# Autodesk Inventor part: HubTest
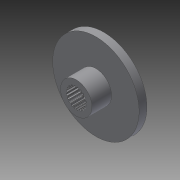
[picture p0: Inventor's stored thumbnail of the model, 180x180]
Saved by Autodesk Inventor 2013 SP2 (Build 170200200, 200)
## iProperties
Created: 2020-02
Part Number: HubTest
Material: Generic
Document SubType Name: Modeling
Designer: DELL
Density: 1 g/cm^3
Author: DELL
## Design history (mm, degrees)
sketch "Sketch1" dims "d2" = 4.61623
  geometry: C1 r 4 at (0, 0); C2 r 2.6 at (0, 0); A1 r 2.308 centre (0, 0) between (0.414, 2.271) and (0.308, 2.287); A2 r 1.037 centre (-0.708, 1.95) between (0.259, 2.327) and (0.255, 2.336); A3 r 0.063 centre (0.317, 2.349) between (0.259, 2.327) and (0.308, 2.287); A4 r 0.062 centre (0.425, 2.332) between (0.414, 2.271) and (0.473, 2.293); A5 r 1.037 centre (1.276, 1.636) between (0.48, 2.301) and (0.473, 2.293); A6 r 1.037 centre (1.276, 1.636) between (0.706, 2.502) and (0.473, 2.293); A7 r 2.6 centre (0, 0) between (0.706, 2.502) and (0.102, 2.598); 2 further points
  constraints: 14 point on circle, 9 centre point, 5 coincident, 6 other
  dimensions: "d3" = 8 diameter of C1; "d8" = 5.2 diameter of C2
extrude "Extrusion1" new body sketch "Sketch1" distance "d4" = 5; taper "d5" = 0 deg
sketch "Sketch5"
  geometry: C1 r 2.6 at (0, 0) reference; 1 further point
extrude "Extrusion4" join sketch "Sketch5" distance "d32" = 1.5; taper "d33" = 0 deg
sketch "Sketch2"
  geometry: L1 (0, -5.6)-(0, 5.6) reference; A1 r 2.6 centre (0, 0) between (0.306, 2.582) and (-0.306, 2.582); A2 r 0.063 centre (-0.055, 2.37) between (-0.108, 2.338) and (-0.053, 2.308); A3 r 0.062 centre (0.055, 2.37) between (0.053, 2.308) and (0.108, 2.338); A4 r 2.308 centre (0, 0) between (0.053, 2.308) and (-0.053, 2.308); A5 r 1.126 centre (1.074, 1.759) between (0.306, 2.582) and (0.108, 2.338); A6 r 1.126 centre (-1.074, 1.759) between (-0.108, 2.338) and (-0.306, 2.582); 1 further point
  constraints: 12 point on circle, 6 centre point, 2 coincident, 1 horizontal alignment, 1 symmetric about line, 1 other
  dimensions: "d9" = 2.6 radius of A1; "d10" = 2.30812 radius of A4; "d11" = 0.0625 radius of A2; "d12" = 0.0625 radius of A3; "d13" = 0.05465 distance from line of A2.centre L1; "d14" = 0.05465 distance from line of L1 A3.centre; "d15" = 2.36999 vertical distance of A2.centre point (0, 0); "d16" = 1.75901 vertical distance of A5.centre point (0, 0); "d17" = 1.07399 horizontal distance of A5.centre point (0, 0); "d18" = 1.12592 radius of A5
extrude "Extrusion2" join sketch "Sketch2" distance "d19" = 3.25; taper "d20" = 0 deg
sketch "Sketch3"
  geometry: C1 r 11 at (0, 0); 1 further point
  constraints: 1 centre point, 1 coincident
  dimensions: "d21" = 22 diameter of C1
extrude "Extrusion3" join sketch "Sketch3" distance "d23" = 2; taper "d24" = 0 deg
sketch "Sketch4"
  geometry: 2 further points
  constraints: 1 coincident
hole "Hole1" sketch "Sketch4" at (0, 0) diameter "d25" = 2.8; stored, may be unused: countersink angle "d29" = 90 deg, drill point angle "d31" = 0 deg; dims "d26" = 6, "d27" = 5, "d28" = 1.75, "d30" = 4
body "Solid1"
pattern_circular "Circular Pattern1" dims angle "d35" = 360 deg
